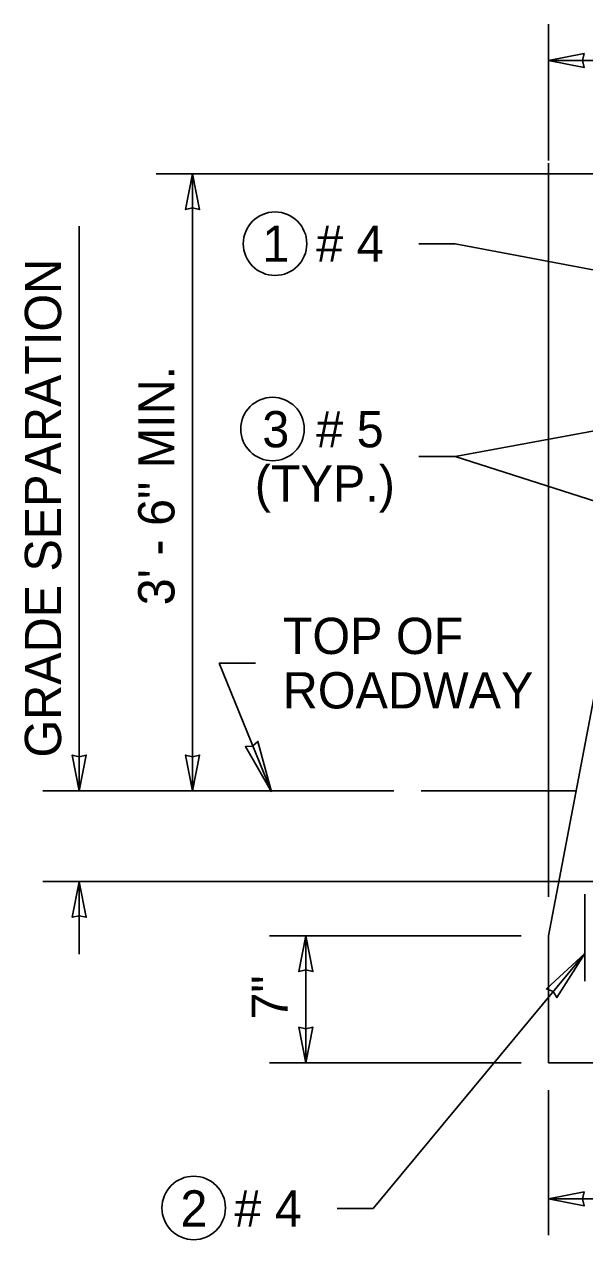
# Model space of a CAD drawing. Extents: x 99862 to 103151, y 100000 to 102076.
# Drawn here: x 100708 to 100955, y 100432 to 100968 of the extents above; entities that cross this region are included whole.
import ezdxf

# ---------------------------------------------------------------- set-up
doc = ezdxf.new("R2010")
doc.units = 0
for name, color, linetype in [('Level 10', 7, 'Continuous'), ('Level 15', 7, 'Continuous'), ('Level 2', 7, 'Continuous'), ('Level 20', 7, 'Continuous'), ('Level 8', 7, 'Continuous')]:
    doc.layers.add(name, color=color, linetype=linetype)

msp = doc.modelspace()

# ---------------------------------------------------------------- linework, layer by layer
at = {"layer": 'Level 10'}
msp.add_line((100954.91, 100546.26), (100954.91, 100584.62), dxfattribs=at)
at = {"layer": 'Level 15'}
for p, q in [((100938.91, 100968.26), (100938.91, 100908.26)), ((101002.92, 100952.26), (100938.92, 100952.26)), ((100938.91, 100907.01), (100938.91, 100583.53)), ((100990.7, 100902.26), (100765.96, 100902.26)), ((100781.95, 100630.26), (100781.95, 100902.26)), ((100731.95, 100879.18), (100731.95, 100630.26)), ((100881.76, 100871.52), (100897.76, 100871.52)), ((101005.36, 100851.02), (100897.76, 100871.52)), ((100995.84, 100795.82), (100897.76, 100777.71)), ((100881.76, 100777.71), (100897.76, 100777.71)), ((101368.44, 100626.52), (100897.76, 100777.71)), ((100816.71, 100629.78), (100793.73, 100686.56)), ((100793.73, 100686.56), (100809.73, 100686.56)), ((100870.71, 100630.26), (100715.96, 100630.26)), ((100731.95, 100558.17), (100731.95, 100590.17)), ((100926.91, 100566.26), (100815.95, 100566.26)), ((100831.95, 100510.26), (100831.95, 100566.26)), ((100954.91, 100558.53), (100861.66, 100446.07)), ((100926.91, 100510.26), (100815.95, 100510.26)), ((100926.91, 100510.26), (100922.69, 100510.26)), ((100938.91, 100498.27), (100938.91, 100434.26)), ((100938.91, 100450.26), (101402.92, 100450.26)), ((100845.66, 100446.07), (100861.66, 100446.07))]:
    msp.add_line(p, q, dxfattribs=at)
for points in [[(100938.92, 100952.26), (100954.64, 100949.18), (100953.92, 100952.26), (100954.64, 100955.35)], [(100781.95, 100902.26), (100785.03, 100886.54), (100781.95, 100887.27), (100778.87, 100886.54)], [(100816.71, 100629.78), (100810.75, 100652.02), (100808.39, 100649.9), (100805.23, 100649.74)], [(100731.95, 100630.26), (100735.03, 100645.99), (100731.95, 100645.26), (100728.86, 100645.99)], [(100781.95, 100630.26), (100785.03, 100645.99), (100781.95, 100645.26), (100778.87, 100645.99)], [(100731.95, 100590.17), (100735.03, 100574.45), (100731.95, 100575.17), (100728.86, 100574.45)], [(100831.95, 100566.26), (100835.03, 100550.54), (100831.95, 100551.27), (100828.86, 100550.54)], [(100954.91, 100558.53), (100942.64, 100539.05), (100941.01, 100541.77), (100938.04, 100542.86)], [(100831.95, 100510.26), (100835.03, 100525.99), (100831.95, 100525.26), (100828.86, 100525.99)], [(100938.91, 100450.26), (100954.64, 100447.18), (100953.91, 100450.26), (100954.64, 100453.35)]]:
    msp.add_lwpolyline(points, close=True, dxfattribs=at)
at = {"layer": 'Level 2'}
for p, q in [((101001.79, 100896.37), (100938.91, 100566.26)), ((100938.91, 100566.26), (100938.91, 100510.26)), ((100944.91, 100510.26), (100938.91, 100510.26)), ((100944.91, 100510.26), (101396.92, 100510.26))]:
    msp.add_line(p, q, dxfattribs=at)
at = {"layer": 'Level 20'}
for centre in [(100818.33, 100871.51), (100817.21, 100789.77), (100782.46, 100446.28)]:
    msp.add_circle(centre, 14, dxfattribs=at)
at = {"layer": 'Level 8'}
for p, q in [((100951.1, 100630.26), (100882.71, 100630.26)), ((100715.96, 100590.26), (101509.12, 100590.26))]:
    msp.add_line(p, q, dxfattribs=at)

# ---------------------------------------------------------------- texts
at = {"layer": 'Level 20'}
for s, p in [('1  # 4', (100812.71, 100863.52)), ('3  # 5', (100812.71, 100781.71)), ('(TYP.)', (100809.39, 100757.71)), ('TOP OF', (100821.74, 100690.56)), ('ROADWAY', (100821.74, 100666.56)), ('2  # 4', (100776.61, 100438.07))]:
    msp.add_text(s, height=16, dxfattribs=at).set_placement(p)
for s, p in [('GRADE SEPARATION', (100723.96, 100644.9)), ('3\' - 6" MIN.', (100773.96, 100712.05)), ('7"', (100823.96, 100529.34))]:
    msp.add_text(s, height=16, rotation=90, dxfattribs=at).set_placement(p)

doc.saveas('drawing.dxf')
